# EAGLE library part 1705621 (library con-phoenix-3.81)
MKDSD 1,5/10-3,81 Printklemme Nennstrom: 8 A Bemessungsspannung: 200 V Raster: 3,81 mm Polzahl: 12 Montageart: Löten Anschlussart: Schraubanschluss Anschlussrichtung vom Leiter zur Platine: 0° Source: http://eshop.phoenixcontact.com .. 1705621.pdf
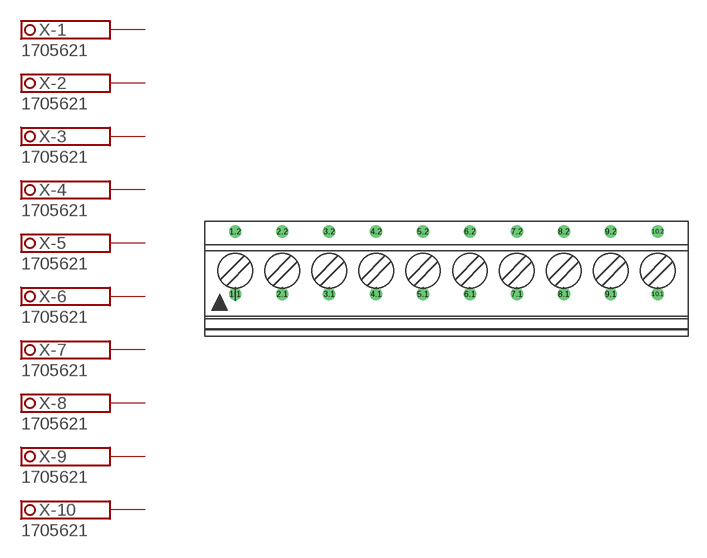
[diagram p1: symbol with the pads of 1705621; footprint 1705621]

Designator prefix X; gates -1=SCHRAUBKLEMME_2 -2=SCHRAUBKLEMME_2 -3=SCHRAUBKLEMME_2 -4=SCHRAUBKLEMME_2 -5=SCHRAUBKLEMME_2 -6=SCHRAUBKLEMME_2 -7=SCHRAUBKLEMME_2 -8=SCHRAUBKLEMME_2 -9=SCHRAUBKLEMME_2 -10=SCHRAUBKLEMME_2

## 1705621 (OC_FARNELL: unknown; OC_NEWARK: unknown)  [1705621]
1.1  -1:1A  pas
1.2  -1:1B  pas
2.1  -2:1A  pas
2.2  -2:1B  pas
3.1  -3:1A  pas
3.2  -3:1B  pas
4.1  -4:1A  pas
4.2  -4:1B  pas
5.1  -5:1A  pas
5.2  -5:1B  pas
6.1  -6:1A  pas
6.2  -6:1B  pas
7.1  -7:1A  pas
7.2  -7:1B  pas
8.1  -8:1A  pas
8.2  -8:1B  pas
9.1  -9:1A  pas
9.2  -9:1B  pas
10.1  -10:1A  pas
10.2  -10:1B  pas

## Footprint 1705621 (pad centres in mm)
MKDSD 1,5/10-3,81 Printklemme Nennstrom: 8 A Bemessungsspannung: 200 V Raster: 3,81 mm Polzahl: 10 Montageart: Löten Anschlussart: Schraubanschluss Anschlussrichtung vom Leiter zur Platine: 0°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
drill 0.5 pad 0.9 round: 1.1 -17.145,-1.25; 1.2 -17.145,3.83; 2.1 -13.335,-1.25; 2.2 -13.335,3.83; 3.1 -9.525,-1.25; 3.2 -9.525,3.83; 4.1 -5.715,-1.25; 4.2 -5.715,3.83; 5.1 -1.905,-1.25; 5.2 -1.905,3.83; 6.1 1.905,-1.25; 6.2 1.905,3.83; 7.1 5.715,-1.25; 7.2 5.715,3.83; 8.1 9.525,-1.25; 8.2 9.525,3.83; 9.1 13.335,-1.25; 9.2 13.335,3.83; 10.1 17.145,-1.25; 10.2 17.145,3.83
